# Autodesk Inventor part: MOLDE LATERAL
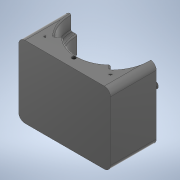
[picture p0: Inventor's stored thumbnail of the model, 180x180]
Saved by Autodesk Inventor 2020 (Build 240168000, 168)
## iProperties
Created: 2022-09
Part Number: MOLDE LATERAL
Material: PVC, no plastificado
Document SubType Name: Modeling
Designer: SEBAS
Density: 1.29 g/cm^3
Appearance: Suave - Negro
Author: SEBAS
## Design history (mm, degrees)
sketch "Boceto3"
  geometry: L1 (37, 58)-(37, 0); L2 (37, 0)-(27, 0); L3 (27, 0)-(27, 5); L4 (27, 5)-(32, 5); L5 (32, 5)-(32, 12); L6 (32, 12)-(27, 12); L7 (27, 12)-(27, 27); L8 (27, 27)-(32, 27); L9 (32, 27)-(32, 31); L10 (32, 31)-(27, 31); L11 (27, 31)-(27, 46); L12 (27, 46)-(32, 46); L13 (32, 46)-(32, 53); L14 (32, 53)-(27, 53); L15 (27, 53)-(27, 58); L16 (27, 58)-(37, 58); L17 (0, 0)-(0, 55); L18 (27, 5)-(27, 12); L19 (27, 27)-(27, 31); L20 (27, 53)-(27, 46); L21 (32, 53)-(32, 58); L22 (32, 5)-(32, 0)
  constraints: 44 end point, 10 perpendicular, 8 point on line, 5 collinear, 3 vertical, 2 horizontal alignment, 2 midpoint, 1 horizontal, 1 vertical alignment
  dimensions: "d27" = 32 distance from line of L17.start L5; "d28" = 10 distance of L1.end L2.end; "d29" = 5 distance of L4.end L3.end; "d30" = 5 distance of L14.end L15.end; "d33" = 4 distance of L8.end L9.end; "d34" = 15 distance of L10.end L11.end; "d35" = 7 distance of L4.end L5.end
sketch "Boceto4"
  geometry: L1 (0, -13.5)-(0, 13.5); L2 (37, 37)-(-37, 37); L3 (-37, 37)-(-37, -37); L4 (-37, -37)-(37, -37); L5 (37, -37)-(37, 37); L6 (37, 37)-(-37, -37); L7 (-37, 37)-(37, -37); L8 (-27, 27)-(27, 27); L9 (27, 27)-(27, -27); L10 (27, -27)-(-27, -27); L11 (-27, -27)-(-27, 27); L12 (-27, 27)-(27, -27); L13 (27, 27)-(-27, -27); L14 (37, 0)-(-37, 0); 4 further points
  constraints: 28 end point, 7 midpoint, 4 parallel, 4 perpendicular, 2 horizontal, 1 coincident
  dimensions: "d38" = 37 horizontal distance of L2.end point (0, 0); "d39" = 10 distance between parallel lines of L2 L8
revolve "Revolución2" stored, may be unused: angle "d40" = 180 deg
extrude "Extrusión2" join sketch "Boceto4" stored distance "d41" = 10; taper "d42" = 0 deg
revolve "Revolución3" stored, may be unused: angle "d43" = 90 deg
fillet "Empalme2" dims "d44" = 5
sketch "Boceto5"
  geometry: L1 (5, 5)-(0, 5) reference; L2 (0, 5)-(0, 0) reference; L3 (0, 0)-(5, 0) reference; L4 (5, 0)-(5, -7) reference; L5 (5, -7)-(0, -7) reference; L6 (0, -7)-(0, -22) reference; L7 (0, -22)-(5, -22) reference; L8 (5, -22)-(5, -26) reference; L9 (5, -26)-(0, -26) reference; L10 (0, -26)-(0, -41) reference; L11 (0, -41)-(5, -41) reference; L12 (5, -41)-(5, -48) reference; L13 (5, -48)-(0, -48) reference; L14 (0, -48)-(0, -53) reference; L15 (0, -53)-(5, -53) reference; L16 (10, -48)-(10, 0) reference; L17 (-64, -48)-(-64, 0) reference; L18 (-54, -53)-(-59, -53) reference; L19 (-54, -48)-(-54, -53) reference; L20 (-54, -48)-(-59, -48) reference; L21 (-59, -48)-(-59, -41) reference; L22 (-59, -41)-(-54, -41) reference; L23 (-54, -26)-(-54, -41) reference; L24 (-54, -26)-(-59, -26) reference; L25 (-59, -26)-(-59, -22) reference; L26 (-59, -22)-(-54, -22) reference; L27 (-54, -7)-(-54, -22) reference; L28 (-54, -7)-(-59, -7) reference; L29 (-59, -7)-(-59, 0) reference; L30 (-59, 0)-(-54, 0) reference; L31 (-54, 5)-(-54, 0) reference; L32 (-59, 5)-(-54, 5) reference; L33 (0, -26)-(0, -41) reference; L34 (0, -33.5)-(10, -33.5); L35 (0, -7)-(0, -22) reference; L36 (0, -14.5)-(10, -14.5); L37 (-54, -33.5)-(-64, -33.5); L38 (-54, -7)-(-54, -22) reference; L39 (-54, -14.5)-(-64, -14.5); L40 (-64, -48)-(-64, 0) reference; L41 (7.5, -31)-(2.5, -31); L42 (2.5, -31)-(2.5, -36); L43 (2.5, -36)-(7.5, -36); L44 (7.5, -36)-(7.5, -31); L45 (7.5, -31)-(2.5, -36); L46 (2.5, -31)-(7.5, -36); L47 (-56, -30.5)-(-62, -30.5); L48 (-62, -30.5)-(-62, -36.5); L49 (-62, -36.5)-(-56, -36.5); L50 (-56, -36.5)-(-56, -30.5); L51 (-56, -30.5)-(-62, -36.5); L52 (-62, -30.5)-(-56, -36.5); L53 (-56.5, -12)-(-61.5, -12); L54 (-61.5, -12)-(-61.5, -17); L55 (-61.5, -17)-(-56.5, -17); L56 (-56.5, -17)-(-56.5, -12); L57 (-56.5, -12)-(-61.5, -17); L58 (-61.5, -12)-(-56.5, -17); L59 (8, -11.5)-(2, -11.5); L60 (2, -11.5)-(2, -17.5); L61 (2, -17.5)-(8, -17.5); L62 (8, -17.5)-(8, -11.5); L63 (8, -11.5)-(2, -17.5); L64 (2, -11.5)-(8, -17.5); A1 r 5 centre (5, 0) between (10, 0) and (5, 5) reference; A2 r 5 centre (5, -48) between (5, -53) and (10, -48) reference; A3 r 5 centre (-59, 0) between (-59, 5) and (-64, 0) reference; A4 r 5 centre (-59, -48) between (-64, -48) and (-59, -53) reference; 5 further points; 1 other entity
  constraints: 56 end point, 15 midpoint, 8 parallel, 7 point on line, 6 equal length, 6 perpendicular, 4 horizontal, 2 other
  dimensions: "d45" = 5 distance of L42.end L43.end; "d51" = 6 distance of L48.end L49.end
  node "Contorno proyectado1"
  node "Contorno proyectado2"
extrude "Extrusión3" join sketch "Boceto5" distance "d46" = 4; taper "d47" = 0 deg
extrude "Extrusión4" cut sketch "Boceto5" distance "d48" = 5; taper "d49" = 0 deg
fillet "Empalme3" dims "d50" = 2
sketch "Boceto6"
  geometry: L1 (32, 31)-(-32, 31) reference; L2 (32, 27)-(32, 31) reference; L3 (32, 27)-(-32, 27) reference; L4 (-32, 31)-(-32, 27) reference; L5 (32, 29)-(-32, 29); L6 (-32, 31)-(-32, 27) reference; L7 (12.5, 16.5)-(-12.5, 16.5); L8 (-12.5, 16.5)-(-12.5, 41.5); L9 (-12.5, 41.5)-(12.5, 41.5); L10 (12.5, 41.5)-(12.5, 16.5); L11 (12.5, 16.5)-(-12.5, 41.5); L12 (-12.5, 16.5)-(12.5, 41.5); 2 further points
  constraints: 14 end point, 5 midpoint, 2 parallel, 2 perpendicular, 1 horizontal
  dimensions: "d53" = 25 distance of L8.end L9.end
extrude "Extrusión5" cut sketch "Boceto6" distance "d54" = 33; taper "d55" = 0 deg
fillet "Empalme5" dims "d56" = 2
revolve "Revolución4" stored, may be unused: angle "d58" = 225 deg; dims "d59" = 45 deg
fillet "Empalme7" dims "d60" = 1
fillet "Empalme8" dims "d61" = 1
sketch "Boceto7"
  geometry: L1 (53.202, -14.384)-(51.079, -16.507) reference; L2 (12.921, -16.507)-(10.798, -14.384) reference; C1 r 1.5 at (32, -7.5); A1 r 28 centre (32, -37) between (51.079, -16.507) and (12.921, -16.507) reference; A2 r 31 centre (32, -37) between (53.92, -15.08) and (10.08, -15.08) reference; A3 r 29.5 centre (32, -37) between (52.141, -15.445) and (11.859, -15.445); 3 further points
  constraints: 3 point on circle, 2 centre point, 2 midpoint
  dimensions: "d62" = 3 diameter of C1
extrude "Extrusión6" cut sketch "Boceto7" stored distance "d63" = 10; taper "d64" = 0 deg
node "Sólido2"
node "Contorno proyectado3"
